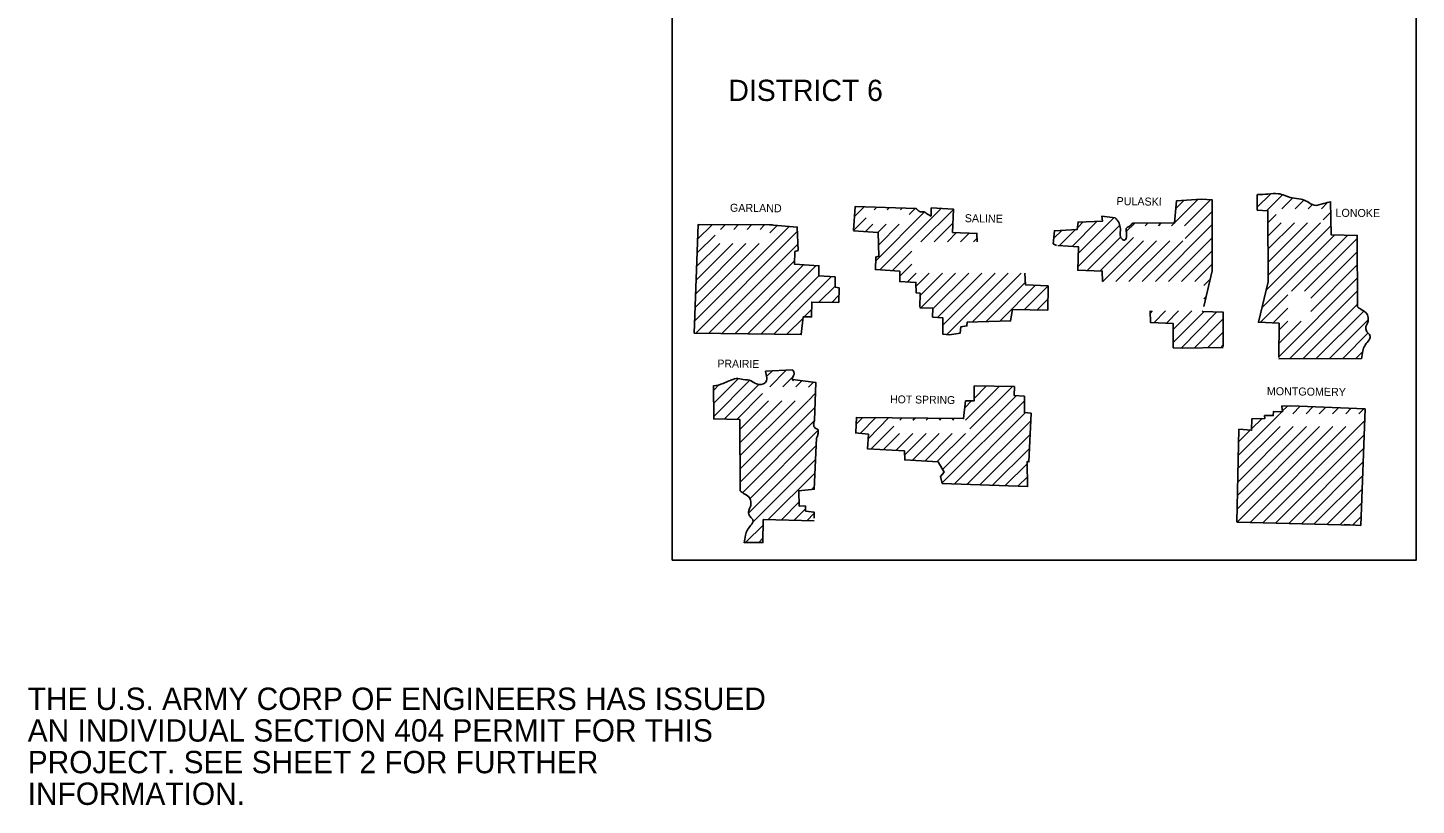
# Model space of a CAD drawing. Extents: x 23481 to 28196, y 1325020 to 1327623.
# Drawn here: x 27242 to 27988, y 1326076 to 1326493 of the extents above; entities that cross this region are included whole.
import ezdxf

# ---------------------------------------------------------------- set-up
doc = ezdxf.new("R2010")
doc.units = 0
doc.layers.add('S_ELECTRIC_UTILITIES_ANNOT', color=7, linetype='Continuous')

msp = doc.modelspace()

# ---------------------------------------------------------------- linework, layer by layer
at = {"layer": 'S_ELECTRIC_UTILITIES_ANNOT'}
for p, q in [((27727.22, 1326392.26), (27727.22, 1326396.66)), ((27693.42, 1326275.06), (27686.32, 1326275.76))]:
    msp.add_line(p, q, dxfattribs=at)
msp.add_lwpolyline([(27587.92, 1326207.46), (27587.92, 1326507.46), (27987.92, 1326507.46), (27987.92, 1326207.46)], close=True, dxfattribs=at)
for points in [[(27685.42, 1326384.46), (27686.32, 1326397.36), (27719.02, 1326396.36)], [(27835.52, 1326388.46), (27858.02, 1326388.56), (27859.02, 1326400.36), (27872.42, 1326401.36)], [(27858.02, 1326388.66), (27870.62, 1326401.26)], [(27858.72, 1326396.36), (27863.02, 1326400.66)], [(27863.42, 1326386.96), (27877.42, 1326400.96)], [(27872.42, 1326401.36), (27878.22, 1326400.96), (27878.32, 1326362.76), (27873.72, 1326343.66)], [(27902.42, 1326397.06), (27909.52, 1326404.06)], [(27902.42, 1326395.46), (27902.42, 1326403.86)], [(27907.52, 1326395.06), (27916.02, 1326403.56)], [(27915.72, 1326396.16), (27921.42, 1326401.86)], [(27922.82, 1326396.16), (27927.42, 1326400.76)], [(27929.92, 1326396.16), (27932.02, 1326398.26)], [(27936.92, 1326396.16), (27940.02, 1326399.26)], [(27941.92, 1326400.06), (27942.12, 1326382.16), (27956.22, 1326381.86), (27956.32, 1326343.46)], [(27685.42, 1326384.46), (27692.22, 1326391.26)], [(27685.92, 1326392.06), (27691.12, 1326397.26)], [(27696.52, 1326395.56), (27698.02, 1326397.06)], [(27697.42, 1326368.16), (27723.42, 1326394.26)], [(27699.62, 1326363.36), (27732.52, 1326396.26)], [(27703.62, 1326395.56), (27704.72, 1326396.76)], [(27710.72, 1326395.56), (27711.62, 1326396.56)], [(27715.32, 1326393.16), (27718.52, 1326396.36)], [(27721.72, 1326378.36), (27739.02, 1326395.66)], [(27727.22, 1326396.66), (27739.12, 1326395.96), (27738.72, 1326383.46), (27751.82, 1326382.96), (27751.92, 1326378.36)], [(27727.22, 1326392.26), (27727.22, 1326392.16)], [(27794.52, 1326376.36), (27794.52, 1326376.46), (27792.72, 1326377.36), (27793.42, 1326384.36), (27805.72, 1326385.06), (27806.12, 1326388.96), (27819.22, 1326389.46), (27818.92, 1326392.16), (27826.12, 1326391.36)], [(27806.32, 1326372.36), (27825.32, 1326391.36)], [(27863.72, 1326380.26), (27878.22, 1326394.76)], [(27914.12, 1326316.26), (27914.22, 1326334.66), (27903.12, 1326335.16), (27908.32, 1326356.86), (27908.22, 1326395.06), (27902.42, 1326395.46)], [(27908.22, 1326388.66), (27912.72, 1326393.16)], [(27937.92, 1326390.16), (27941.92, 1326394.16)], [(27599.72, 1326329.36), (27601.92, 1326387.66), (27641.92, 1326387.46)], [(27600.02, 1326335.76), (27650.92, 1326386.66)], [(27600.72, 1326329.36), (27655.22, 1326383.86)], [(27601.62, 1326379.76), (27609.42, 1326387.56)], [(27601.92, 1326387.06), (27602.42, 1326387.66)], [(27614.02, 1326385.06), (27616.52, 1326387.56)], [(27621.12, 1326385.06), (27623.52, 1326387.46)], [(27628.22, 1326385.06), (27630.62, 1326387.46)], [(27635.22, 1326385.06), (27637.62, 1326387.46)], [(27640.32, 1326387.46), (27655.22, 1326386.36), (27655.62, 1326373.76), (27653.92, 1326373.16), (27653.72, 1326366.46), (27666.82, 1326365.56), (27666.82, 1326360.06), (27675.52, 1326359.56), (27675.62, 1326354.06), (27677.72, 1326353.76), (27677.62, 1326345.86)], [(27640.42, 1326383.16), (27644.32, 1326387.06)], [(27721.12, 1326343.36), (27721.22, 1326350.76), (27719.12, 1326351.06), (27719.02, 1326356.56), (27710.32, 1326357.06), (27710.32, 1326362.56), (27697.22, 1326363.46), (27697.42, 1326370.16), (27699.12, 1326370.76), (27698.72, 1326383.36), (27685.42, 1326384.36)], [(27691.92, 1326383.86), (27695.92, 1326387.86)], [(27698.52, 1326383.36), (27703.02, 1326387.86)], [(27699.02, 1326376.86), (27710.02, 1326387.86)], [(27728.72, 1326378.36), (27738.82, 1326388.46)], [(27735.92, 1326378.36), (27740.82, 1326383.36)], [(27742.92, 1326378.36), (27747.72, 1326383.16)], [(27793.02, 1326380.16), (27797.52, 1326384.66)], [(27796.22, 1326376.36), (27805.02, 1326385.16)], [(27802.92, 1326375.96), (27816.22, 1326389.26)], [(27805.82, 1326385.96), (27808.92, 1326389.06)], [(27806.02, 1326364.96), (27828.52, 1326387.36)], [(27832.02, 1326383.86), (27836.62, 1326388.46)], [(27842.22, 1326386.96), (27843.72, 1326388.46)], [(27847.72, 1326357.06), (27878.22, 1326387.66)], [(27849.32, 1326386.96), (27850.72, 1326388.46)], [(27856.32, 1326386.96), (27857.82, 1326388.46)], [(27907.32, 1326352.36), (27942.12, 1326387.16)], [(27908.32, 1326360.56), (27936.42, 1326388.66)], [(27908.32, 1326367.56), (27929.42, 1326388.66)], [(27908.32, 1326374.66), (27922.42, 1326388.66)], [(27908.32, 1326381.66), (27915.32, 1326388.66)], [(27600.32, 1326343.06), (27634.72, 1326377.46)], [(27600.52, 1326350.36), (27627.62, 1326377.46)], [(27600.82, 1326357.76), (27620.62, 1326377.46)], [(27601.12, 1326365.06), (27613.52, 1326377.46)], [(27601.42, 1326372.46), (27611.02, 1326382.06)], [(27607.72, 1326329.36), (27655.52, 1326377.06)], [(27750.02, 1326378.36), (27751.82, 1326380.16)], [(27819.32, 1326357.06), (27819.12, 1326362.66), (27806.02, 1326363.16), (27806.42, 1326375.66), (27795.22, 1326376.36)], [(27811.12, 1326362.96), (27829.22, 1326381.06)], [(27817.92, 1326362.66), (27836.02, 1326380.76)], [(27819.32, 1326356.96), (27819.42, 1326357.06), (27841.32, 1326378.96)], [(27826.42, 1326357.06), (27848.32, 1326378.96)], [(27833.52, 1326357.06), (27855.42, 1326378.96)], [(27840.62, 1326357.06), (27862.52, 1326378.96)], [(27854.72, 1326357.06), (27878.22, 1326380.56)], [(27905.02, 1326343.06), (27944.02, 1326382.06)], [(27920.92, 1326351.86), (27950.92, 1326381.86)], [(27927.92, 1326351.86), (27956.22, 1326380.16)], [(27614.72, 1326329.16), (27653.72, 1326368.16)], [(27706.22, 1326362.86), (27716.72, 1326373.36)], [(27861.82, 1326357.06), (27878.22, 1326373.56)], [(27931.22, 1326348.06), (27956.22, 1326373.06)], [(27621.72, 1326329.06), (27658.72, 1326366.16)], [(27628.62, 1326328.96), (27665.32, 1326365.66)], [(27635.62, 1326328.86), (27666.82, 1326360.06)], [(27710.32, 1326359.96), (27716.72, 1326366.36)], [(27714.42, 1326356.86), (27719.12, 1326361.56)], [(27719.12, 1326354.56), (27726.12, 1326361.56)], [(27721.22, 1326349.56), (27733.22, 1326361.56)], [(27721.52, 1326342.76), (27740.32, 1326361.56)], [(27728.12, 1326342.36), (27747.42, 1326361.56)], [(27730.72, 1326337.86), (27754.42, 1326361.56)], [(27733.52, 1326333.66), (27761.52, 1326361.56)], [(27735.62, 1326328.56), (27768.62, 1326361.56)], [(27749.42, 1326335.36), (27775.62, 1326361.56)], [(27777.52, 1326361.56), (27777.82, 1326355.36), (27790.02, 1326354.76), (27789.92, 1326341.76)], [(27868.92, 1326357.06), (27878.22, 1326366.46)], [(27931.22, 1326340.96), (27956.22, 1326365.96)], [(27642.62, 1326328.86), (27673.42, 1326359.66)], [(27666.82, 1326345.96), (27675.52, 1326354.66)], [(27756.72, 1326335.56), (27777.72, 1326356.56)], [(27764.02, 1326335.76), (27783.22, 1326355.06)], [(27777.22, 1326341.86), (27790.02, 1326354.76)], [(27873.72, 1326354.86), (27877.22, 1326358.36)], [(27914.22, 1326316.86), (27956.22, 1326358.86)], [(27677.62, 1326345.86), (27663.02, 1326346.06), (27662.92, 1326338.06), (27658.42, 1326338.06), (27657.32, 1326328.56), (27599.72, 1326329.36)], [(27673.82, 1326345.86), (27677.62, 1326349.66)], [(27784.22, 1326341.86), (27789.92, 1326347.56)], [(27873.72, 1326347.76), (27875.02, 1326349.06)], [(27904.22, 1326335.26), (27918.82, 1326349.86)], [(27920.02, 1326315.66), (27956.22, 1326351.86)], [(27658.92, 1326338.06), (27662.92, 1326342.06)], [(27737.12, 1326328.46), (27733.52, 1326328.76), (27733.52, 1326337.56), (27727.92, 1326337.96), (27728.12, 1326342.76), (27721.12, 1326342.86)], [(27789.92, 1326341.76), (27770.82, 1326342.06), (27769.92, 1326335.96), (27746.62, 1326335.26), (27746.42, 1326333.26), (27743.12, 1326332.66), (27742.72, 1326329.26), (27737.12, 1326328.46)], [(27857.22, 1326321.46), (27857.32, 1326334.46), (27845.12, 1326335.06), (27844.82, 1326341.26)], [(27844.92, 1326340.16), (27846.02, 1326341.26)], [(27846.82, 1326334.96), (27853.12, 1326341.26)], [(27853.62, 1326334.66), (27860.22, 1326341.26)], [(27857.22, 1326324.26), (27874.02, 1326340.96)], [(27857.32, 1326331.36), (27867.22, 1326341.26)], [(27861.52, 1326321.36), (27880.82, 1326340.76)], [(27873.22, 1326341.26), (27873.12, 1326341.06), (27884.22, 1326340.56), (27884.12, 1326322.16)], [(27911.02, 1326334.96), (27918.82, 1326342.76)], [(27927.12, 1326315.66), (27956.22, 1326344.76)], [(27934.22, 1326315.66), (27959.62, 1326341.06)], [(27649.52, 1326328.66), (27658.32, 1326337.46)], [(27868.62, 1326321.36), (27884.12, 1326336.96)], [(27914.22, 1326323.96), (27926.02, 1326335.76)], [(27914.22, 1326331.06), (27918.92, 1326335.76)], [(27941.32, 1326315.66), (27961.92, 1326336.36)], [(27656.52, 1326328.56), (27657.42, 1326329.56)], [(27875.72, 1326321.46), (27884.12, 1326329.86)], [(27882.82, 1326321.46), (27884.12, 1326322.86)], [(27948.42, 1326315.76), (27962.12, 1326329.46)], [(27862.02, 1326321.36), (27857.22, 1326321.46)], [(27884.12, 1326321.56), (27862.02, 1326321.36)], [(27958.52, 1326315.76), (27914.12, 1326315.56)], [(27955.52, 1326315.76), (27959.22, 1326319.46)], [(27638.12, 1326308.96), (27652.62, 1326309.66)], [(27639.12, 1326306.36), (27641.82, 1326309.06)], [(27640.42, 1326300.56), (27649.32, 1326309.46)], [(27610.12, 1326298.56), (27613.32, 1326301.76)], [(27624.52, 1326244.56), (27624.42, 1326282.96), (27610.32, 1326283.26), (27610.12, 1326301.16)], [(27610.22, 1326291.56), (27623.42, 1326304.76)], [(27610.32, 1326284.66), (27629.52, 1326303.86)], [(27615.92, 1326283.16), (27634.52, 1326301.76)], [(27647.42, 1326300.56), (27653.12, 1326306.26)], [(27652.62, 1326304.46), (27665.12, 1326302.86), (27664.42, 1326282.46)], [(27654.52, 1326300.56), (27657.72, 1326303.76)], [(27661.22, 1326300.26), (27664.02, 1326302.96)], [(27687.02, 1326284.06), (27744.62, 1326283.46), (27745.72, 1326292.96), (27750.22, 1326292.96), (27750.32, 1326300.96), (27771.92, 1326300.66), (27771.72, 1326295.86), (27777.32, 1326295.46), (27777.32, 1326286.66), (27780.92, 1326286.36), (27779.72, 1326260.16), (27778.82, 1326260.46), (27778.92, 1326246.86)], [(27745.72, 1326282.66), (27763.82, 1326300.76)], [(27748.02, 1326277.96), (27770.82, 1326300.66)], [(27750.22, 1326294.26), (27756.82, 1326300.86)], [(27622.72, 1326282.96), (27636.62, 1326296.86)], [(27624.42, 1326277.56), (27639.82, 1326292.96)], [(27624.52, 1326256.46), (27661.02, 1326292.96)], [(27624.52, 1326263.56), (27654.02, 1326292.96)], [(27624.52, 1326270.56), (27646.92, 1326292.96)], [(27661.22, 1326293.16), (27664.92, 1326296.86)], [(27733.12, 1326248.86), (27777.32, 1326293.06)], [(27733.32, 1326256.16), (27772.82, 1326295.66)], [(27745.32, 1326289.26), (27748.92, 1326292.96)], [(27624.52, 1326249.36), (27664.62, 1326289.46)], [(27739.82, 1326248.46), (27777.92, 1326286.66)], [(27891.5, 1326227.87), (27892.6, 1326277.77), (27899.4, 1326277.17), (27899.5, 1326283.27), (27906.5, 1326283.47), (27906.4, 1326285.07), (27911.1, 1326285.07), (27911.2, 1326287.27), (27916, 1326287.17), (27915.6, 1326290.17), (27920.6, 1326290.27)], [(27892.3, 1326263.77), (27914.4, 1326285.87)], [(27914.6, 1326286.07), (27915.7, 1326287.17)], [(27915.9, 1326287.37), (27918.7, 1326290.17)], [(27920.6, 1326290.27), (27960.4, 1326288.77)], [(27921.6, 1326286.07), (27925.6, 1326290.07)], [(27928.7, 1326286.07), (27932.4, 1326289.77)], [(27935.8, 1326286.07), (27939.3, 1326289.57)], [(27942.9, 1326286.07), (27946.1, 1326289.27)], [(27950, 1326286.07), (27952.9, 1326288.97)], [(27957, 1326286.07), (27959.7, 1326288.77)], [(27960.4, 1326288.77), (27958.1, 1326225.97)], [(27626.02, 1326243.76), (27664.02, 1326281.86)], [(27686.72, 1326275.96), (27687.02, 1326284.26)], [(27686.92, 1326280.46), (27690.52, 1326284.06)], [(27689.12, 1326275.56), (27697.52, 1326283.96)], [(27693.42, 1326272.76), (27704.52, 1326283.96)], [(27694.82, 1326267.06), (27707.12, 1326279.46)], [(27710.42, 1326282.66), (27711.52, 1326283.86)], [(27717.42, 1326282.66), (27718.52, 1326283.76)], [(27724.52, 1326282.66), (27725.42, 1326283.56)], [(27731.62, 1326282.66), (27732.42, 1326283.46)], [(27738.72, 1326282.66), (27739.42, 1326283.46)], [(27746.62, 1326248.26), (27780.72, 1326282.26)], [(27891.6, 1326227.77), (27891.7, 1326227.87), (27943.1, 1326279.17)], [(27891.7, 1326234.87), (27936, 1326279.17)], [(27891.8, 1326242.07), (27928.9, 1326279.17)], [(27892, 1326249.37), (27921.8, 1326279.17)], [(27892.1, 1326256.57), (27914.7, 1326279.17)], [(27898.6, 1326227.67), (27950.1, 1326279.17)], [(27899.5, 1326278.07), (27904.9, 1326283.37)], [(27905.6, 1326227.57), (27960.2, 1326282.17)], [(27906.4, 1326284.97), (27906.6, 1326285.07)], [(27629.92, 1326240.56), (27666.32, 1326277.06)], [(27665.52, 1326272.86), (27664.32, 1326245.46), (27656.12, 1326244.56), (27656.32, 1326236.46), (27659.62, 1326236.56), (27659.72, 1326233.76), (27664.22, 1326233.26), (27664.32, 1326229.96)], [(27778.92, 1326247.06), (27733.12, 1326248.66), (27732.22, 1326252.36), (27734.12, 1326254.76), (27731.02, 1326260.16), (27713.02, 1326261.26), (27712.92, 1326266.06), (27693.02, 1326267.16), (27693.42, 1326275.06)], [(27701.52, 1326266.76), (27710.22, 1326275.46)], [(27708.22, 1326266.36), (27717.32, 1326275.46)], [(27713.02, 1326264.06), (27724.42, 1326275.46)], [(27717.12, 1326261.06), (27731.52, 1326275.46)], [(27723.72, 1326260.66), (27738.52, 1326275.46)], [(27730.32, 1326260.26), (27745.62, 1326275.46)], [(27753.52, 1326247.96), (27780.32, 1326274.86)], [(27892.4, 1326270.97), (27898.7, 1326277.27)], [(27912.4, 1326227.37), (27959.9, 1326274.77)], [(27629.02, 1326232.66), (27665.32, 1326268.96)], [(27760.22, 1326247.66), (27780.02, 1326267.46)], [(27919.4, 1326227.17), (27959.6, 1326267.47)], [(27631.52, 1326228.06), (27665.02, 1326261.56)], [(27767.02, 1326247.46), (27778.82, 1326259.16)], [(27926.2, 1326226.97), (27959.3, 1326260.07)], [(27639.62, 1326229.16), (27664.72, 1326254.16)], [(27773.82, 1326247.16), (27778.92, 1326252.16)], [(27933.1, 1326226.87), (27959.1, 1326252.77)], [(27662.82, 1326245.26), (27664.32, 1326246.76)], [(27940.1, 1326226.67), (27958.8, 1326245.47)], [(27646.52, 1326228.96), (27656.32, 1326238.66)], [(27653.42, 1326228.76), (27659.72, 1326235.06)], [(27946.9, 1326226.47), (27958.5, 1326238.07)], [(27664.32, 1326228.46), (27636.92, 1326229.16), (27636.72, 1326216.86), (27626.72, 1326216.86)], [(27627.42, 1326216.96), (27637.02, 1326226.46)], [(27660.32, 1326228.56), (27664.32, 1326232.66)], [(27954.4, 1326226.27), (27891.7, 1326227.87)], [(27949.4, 1326226.37), (27949.4, 1326226.57), (27958.1, 1326225.97)], [(27953.9, 1326226.37), (27958.2, 1326230.77)], [(27634.52, 1326216.96), (27636.72, 1326219.16)]]:
    msp.add_lwpolyline(points, dxfattribs=at)
for points in [[(27902.62, 1326403.86), (27908.22, 1326404.06), (27913.72, 1326404.26), (27917.22, 1326403.26), (27921.22, 1326401.96), (27925.92, 1326401.36), (27929.22, 1326400.06), (27933.12, 1326398.06), (27938.12, 1326398.96), (27941.92, 1326399.96)], [(27719.02, 1326396.36), (27720.22, 1326395.26), (27721.52, 1326394.46), (27723.12, 1326394.56), (27724.62, 1326393.66), (27727.22, 1326392.26)], [(27826.12, 1326391.36), (27827.82, 1326389.16), (27828.82, 1326386.16), (27828.82, 1326382.76), (27829.62, 1326379.96), (27831.22, 1326379.36), (27832.22, 1326381.76), (27832.02, 1326384.16), (27832.02, 1326385.56), (27833.72, 1326386.76), (27835.52, 1326388.46)], [(27956.32, 1326343.46), (27958.82, 1326341.76), (27961.42, 1326339.76), (27962.12, 1326337.06), (27961.92, 1326335.16), (27961.12, 1326333.56), (27960.92, 1326331.06), (27962.12, 1326329.26), (27963.22, 1326327.76), (27962.12, 1326325.06), (27960.22, 1326322.56), (27959.22, 1326319.76), (27958.52, 1326315.56)], [(27610.12, 1326301.06), (27610.22, 1326301.06), (27615.32, 1326302.36), (27618.62, 1326303.76), (27622.42, 1326304.96), (27626.22, 1326304.46), (27630.52, 1326303.66), (27633.22, 1326302.06), (27638.12, 1326302.76), (27638.12, 1326308.96)], [(27652.72, 1326309.66), (27653.52, 1326308.06), (27653.22, 1326306.66), (27652.62, 1326304.46), (27653.12, 1326303.76)], [(27664.42, 1326282.46), (27664.02, 1326280.46), (27664.82, 1326278.36), (27666.22, 1326277.66), (27666.42, 1326275.66), (27665.92, 1326273.66), (27665.52, 1326272.86)], [(27626.72, 1326216.66), (27627.42, 1326220.86), (27628.42, 1326223.66), (27630.32, 1326226.16), (27631.42, 1326228.86), (27630.32, 1326230.36), (27629.12, 1326232.16), (27629.32, 1326234.66), (27630.12, 1326236.26), (27630.32, 1326238.16), (27629.62, 1326240.86), (27627.02, 1326242.86), (27624.52, 1326244.56)]]:
    msp.add_spline(points, degree=3, dxfattribs=at)

# ---------------------------------------------------------------- texts
for s, height, p in [('DISTRICT 6', 11.4, (27618.22, 1326454.06)), ('THE U.S. ARMY CORP OF ENGINEERS HAS ISSUED', 12, (27241.58, 1326126.95)), ('AN INDIVIDUAL SECTION 404 PERMIT FOR THIS', 12, (27241.58, 1326109.95)), ('PROJECT. SEE SHEET 2 FOR FURTHER', 12, (27241.58, 1326092.95)), ('INFORMATION.', 12, (27241.58, 1326075.95))]:
    msp.add_text(s, height=height, dxfattribs=at).set_placement(p)
for s, height, rotation, p in [('GARLAND', 4.301, 359.36576, (27619.02, 1326394.56)), ('PULASKI', 4.301, 359.05305, (27826.82, 1326398.16)), ('SALINE', 4.301, 359.14914, (27745.22, 1326388.96)), ('LONOKE', 4.301, 359.49742, (27944.52, 1326391.86)), ('PRAIRIE', 4.201, 359.21158, (27612.32, 1326310.96)), ('MONTGOMERY', 4.301, 359.29442, (27907.6, 1326296.07)), ('HOT SPRING', 4.201, 359.22157, (27705.12, 1326291.76))]:
    msp.add_text(s, height=height, rotation=rotation, dxfattribs=at).set_placement(p)

doc.saveas('drawing.dxf')
